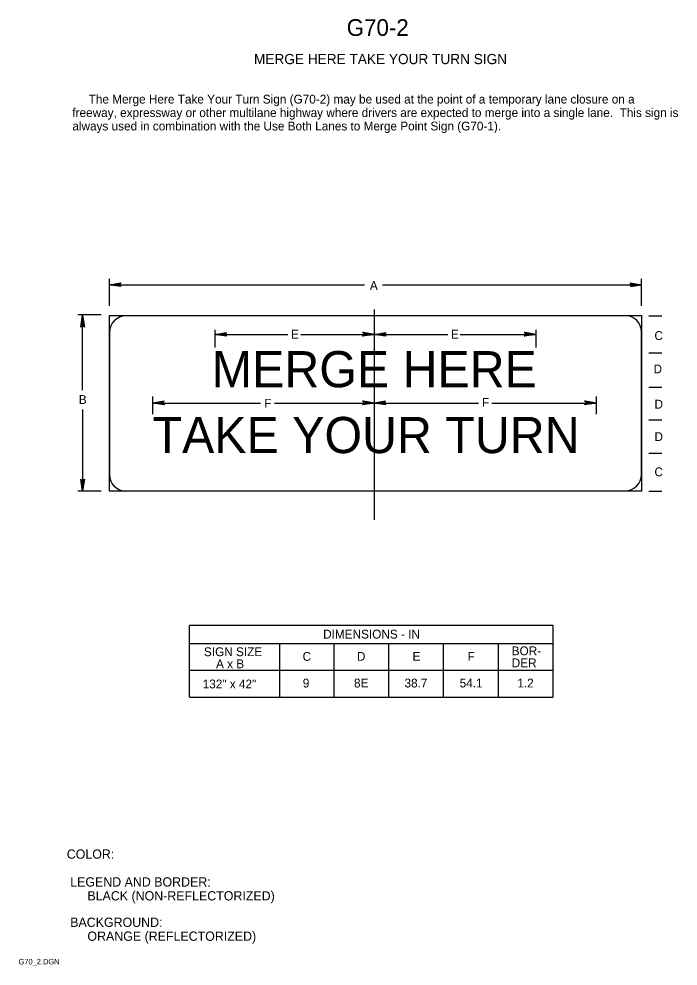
# Model space of a CAD drawing. Extents: x 0.013 to 0.19, y 0.004 to 0.259.
import ezdxf

# ---------------------------------------------------------------- set-up
doc = ezdxf.new("R2010")
doc.units = 0
doc.layers.add('1', color=7, linetype='Continuous')
doc.layers.add('3', color=7, linetype='Continuous')

msp = doc.modelspace()

# ---------------------------------------------------------------- linework, layer by layer
at = {"layer": '1'}
for p, q in [((0.037, 0.182), (0.037, 0.18925)), ((0.1805, 0.182), (0.1805, 0.18925)), ((0.037, 0.18763), (0.10576, 0.18763)), ((0.11064, 0.18763), (0.1805, 0.18763)), ((0.03475, 0.1795), (0.0285, 0.1795)), ((0.02973, 0.15925), (0.02973, 0.17936)), ((0.037, 0.132), (0.037, 0.17938)), ((0.037, 0.17938), (0.1805, 0.17938)), ((0.1085, 0.12425), (0.1085, 0.181)), ((0.1805, 0.17938), (0.1805, 0.132)), ((0.1825, 0.17925), (0.186, 0.17925)), ((0.0655, 0.17075), (0.0655, 0.1755)), ((0.0655, 0.17425), (0.08513, 0.17425)), ((0.08865, 0.17425), (0.1085, 0.17425)), ((0.1085, 0.17075), (0.1085, 0.1755)), ((0.1085, 0.17425), (0.12825, 0.17425)), ((0.1316, 0.17425), (0.15213, 0.17425)), ((0.15213, 0.17075), (0.15213, 0.1755)), ((0.1825, 0.16925), (0.186, 0.16925)), ((0.1825, 0.16), (0.186, 0.16)), ((0.04875, 0.15275), (0.04875, 0.1575)), ((0.1085, 0.15275), (0.1085, 0.1575)), ((0.16837, 0.15275), (0.16837, 0.1575)), ((0.02977, 0.154), (0.02977, 0.13214)), ((0.04875, 0.15575), (0.07774, 0.15575)), ((0.0815, 0.15575), (0.1085, 0.15575)), ((0.1085, 0.15575), (0.1365, 0.15575)), ((0.14016, 0.15575), (0.16828, 0.15575)), ((0.1825, 0.15125), (0.186, 0.15125)), ((0.1825, 0.14225), (0.186, 0.14225)), ((0.03475, 0.132), (0.0285, 0.132)), ((0.1805, 0.132), (0.037, 0.132)), ((0.1825, 0.132), (0.186, 0.132))]:
    msp.add_line(p, q, dxfattribs=at)
for points in [[(0.04, 0.18738), (0.03975, 0.18738), (0.037, 0.18763), (0.04, 0.18738), (0.04, 0.18713), (0.037, 0.18763), (0.03975, 0.18788), (0.04, 0.18788), (0.037, 0.18763), (0.04, 0.18813), (0.04, 0.18788)], [(0.1775, 0.18788), (0.17775, 0.18763), (0.1805, 0.18763), (0.1775, 0.18788), (0.1775, 0.18813), (0.1805, 0.18763), (0.17775, 0.18738), (0.1775, 0.18713), (0.1805, 0.18763), (0.1775, 0.18713), (0.1775, 0.18713)], [(0.02925, 0.1765), (0.0295, 0.1765), (0.02975, 0.1795), (0.02925, 0.1765), (0.02925, 0.17625), (0.02975, 0.1795), (0.02975, 0.1765), (0.03, 0.1765), (0.02975, 0.1795), (0.03025, 0.17625), (0.03, 0.1765)], [(0.0685, 0.174), (0.06825, 0.174), (0.0655, 0.17425), (0.0685, 0.174), (0.0685, 0.17375), (0.0655, 0.17425), (0.06825, 0.1745), (0.0685, 0.1745), (0.0655, 0.17425), (0.0685, 0.17475), (0.0685, 0.1745)], [(0.1055, 0.17475), (0.1055, 0.1745), (0.1085, 0.17425), (0.1055, 0.17475), (0.10525, 0.17475), (0.1085, 0.17425), (0.1055, 0.174), (0.1055, 0.174), (0.1085, 0.17425), (0.10525, 0.17375), (0.1055, 0.174)], [(0.1115, 0.174), (0.11125, 0.174), (0.1085, 0.17425), (0.1115, 0.174), (0.1115, 0.17375), (0.1085, 0.17425), (0.11125, 0.1745), (0.1115, 0.1745), (0.1085, 0.17425), (0.1115, 0.17475), (0.1115, 0.1745)], [(0.14913, 0.17475), (0.14913, 0.1745), (0.15213, 0.17425), (0.14913, 0.17475), (0.14888, 0.17475), (0.15213, 0.17425), (0.14913, 0.174), (0.14913, 0.174), (0.15213, 0.17425), (0.14888, 0.17375), (0.14913, 0.174)], [(0.05175, 0.1555), (0.0515, 0.15575), (0.04875, 0.15575), (0.05175, 0.1555), (0.05175, 0.15525), (0.04875, 0.15575), (0.0515, 0.156), (0.05175, 0.15625), (0.04875, 0.15575), (0.05175, 0.15625), (0.05175, 0.15625)], [(0.1055, 0.15625), (0.1055, 0.156), (0.1085, 0.15575), (0.1055, 0.15625), (0.10525, 0.15625), (0.1085, 0.15575), (0.1055, 0.15575), (0.1055, 0.1555), (0.1085, 0.15575), (0.10525, 0.15525), (0.1055, 0.1555)], [(0.1115, 0.1555), (0.11125, 0.15575), (0.1085, 0.15575), (0.1115, 0.1555), (0.1115, 0.15525), (0.1085, 0.15575), (0.11125, 0.156), (0.1115, 0.15625), (0.1085, 0.15575), (0.1115, 0.15625), (0.1115, 0.15625)], [(0.16537, 0.15625), (0.16537, 0.156), (0.16837, 0.15575), (0.16537, 0.15625), (0.16512, 0.15625), (0.16837, 0.15575), (0.16537, 0.15575), (0.16537, 0.1555), (0.16837, 0.15575), (0.16512, 0.15525), (0.16537, 0.1555)], [(0.03, 0.135), (0.02975, 0.135), (0.02975, 0.132), (0.03, 0.135), (0.03025, 0.13525), (0.02975, 0.132), (0.0295, 0.135), (0.02925, 0.135), (0.02975, 0.132), (0.02925, 0.13525), (0.02925, 0.135)]]:
    msp.add_lwpolyline(points, dxfattribs=at)
at = {"layer": '3'}
for p, q in [((0.17611, 0.17931), (0.04145, 0.17925)), ((0.03703, 0.17483), (0.03703, 0.13645)), ((0.18053, 0.13651), (0.18053, 0.17489)), ((0.04145, 0.13203), (0.17611, 0.13209)), ((0.0585, 0.09575), (0.0585, 0.0765)), ((0.05858, 0.09583), (0.15662, 0.09583)), ((0.15662, 0.09583), (0.15662, 0.07641)), ((0.15662, 0.09083), (0.05858, 0.09083)), ((0.08287, 0.09083), (0.08287, 0.07641)), ((0.0975, 0.09075), (0.0975, 0.0765)), ((0.11225, 0.09075), (0.11225, 0.0765)), ((0.127, 0.09075), (0.127, 0.0765)), ((0.14187, 0.09083), (0.14187, 0.07641)), ((0.05858, 0.08371), (0.15662, 0.08371)), ((0.05858, 0.07641), (0.15662, 0.07641))]:
    msp.add_line(p, q, dxfattribs=at)
for centre, start, end in [((0.04145, 0.17483), 90, 180), ((0.17611, 0.17489), 0, 90), ((0.04145, 0.13645), 180, 270), ((0.17611, 0.13651), 270, 0)]:
    msp.add_arc(centre, 0.00442, start, end, dxfattribs=at)

# ---------------------------------------------------------------- texts
at = {"layer": '1'}
for s, height, p in [('G70-2', 0.0045, (0.101, 0.25475)), ('MERGE HERE TAKE YOUR TURN SIGN', 0.0027503, (0.076, 0.24713)), ('     The Merge Here Take Your Turn Sign (G70-2) may be used at the point of a temporary lane closure on a ', 0.00237525, (0.027, 0.2365)), ('freeway, expressway or other multilane highway where drivers are expected to merge into a single lane.  This sign is', 0.00237525, (0.027, 0.23287)), ('always used in combination with the Use Both Lanes to Merge Point Sign (G70-1).', 0.0023752, (0.027, 0.22925)), ('A', 0.00238, (0.10725, 0.18625)), ('E', 0.00238, (0.086, 0.17313)), ('E', 0.00238, (0.12912, 0.17313)), ('C', 0.00238, (0.184, 0.17275)), ('MERGE HERE', 0.00975, (0.06463, 0.16)), ('D', 0.00238, (0.18375, 0.16375)), ('B', 0.00238, (0.02875, 0.1555)), ('F', 0.00238, (0.07875, 0.1545)), ('F', 0.00238, (0.1375, 0.15475)), ('D', 0.00238, (0.184, 0.15425)), ('TAKE YOUR TURN', 0.00975, (0.04863, 0.14225)), ('D', 0.00238, (0.184, 0.1455)), ('C', 0.00238, (0.184, 0.136)), ('COLOR:', 0.0025, (0.0255, 0.03288)), (' LEGEND AND BORDER:', 0.0024998, (0.0255, 0.02538)), ('      BLACK (NON-REFLECTORIZED)', 0.0024998, (0.0255, 0.02163)), (' BACKGROUND:', 0.0024998, (0.0255, 0.0145)), ('      ORANGE (REFLECTORIZED)', 0.0024998, (0.0255, 0.01075)), ('G70_2.DGN', 0.0015, (0.0125, 0.00438))]:
    msp.add_text(s, height=height, dxfattribs=at).set_placement(p)
at = {"layer": '3'}
for s, height, p in [('DIMENSIONS - IN', 0.0023752, (0.09464, 0.09225)), ('SIGN SIZE', 0.002375, (0.0625, 0.0875)), ('BOR-', 0.002375, (0.1455, 0.08775)), ('C', 0.00238, (0.0891, 0.08625)), ('D', 0.00238, (0.10375, 0.08625)), ('E', 0.00238, (0.11875, 0.08625)), ('F', 0.00238, (0.13359, 0.08625)), ('DER', 0.002375, (0.1455, 0.0845)), ('A x B', 0.002375, (0.06575, 0.08425)), ('132" x 42"', 0.002375, (0.06215, 0.07881)), ('9', 0.00238, (0.08915, 0.07906)), ('8E', 0.002375, (0.10297, 0.07906)), ('38.7', 0.002375, (0.11659, 0.07906)), ('54.1', 0.002375, (0.13146, 0.07906)), ('1.2', 0.002375, (0.14701, 0.07906))]:
    msp.add_text(s, height=height, dxfattribs=at).set_placement(p)

doc.saveas('drawing.dxf')
